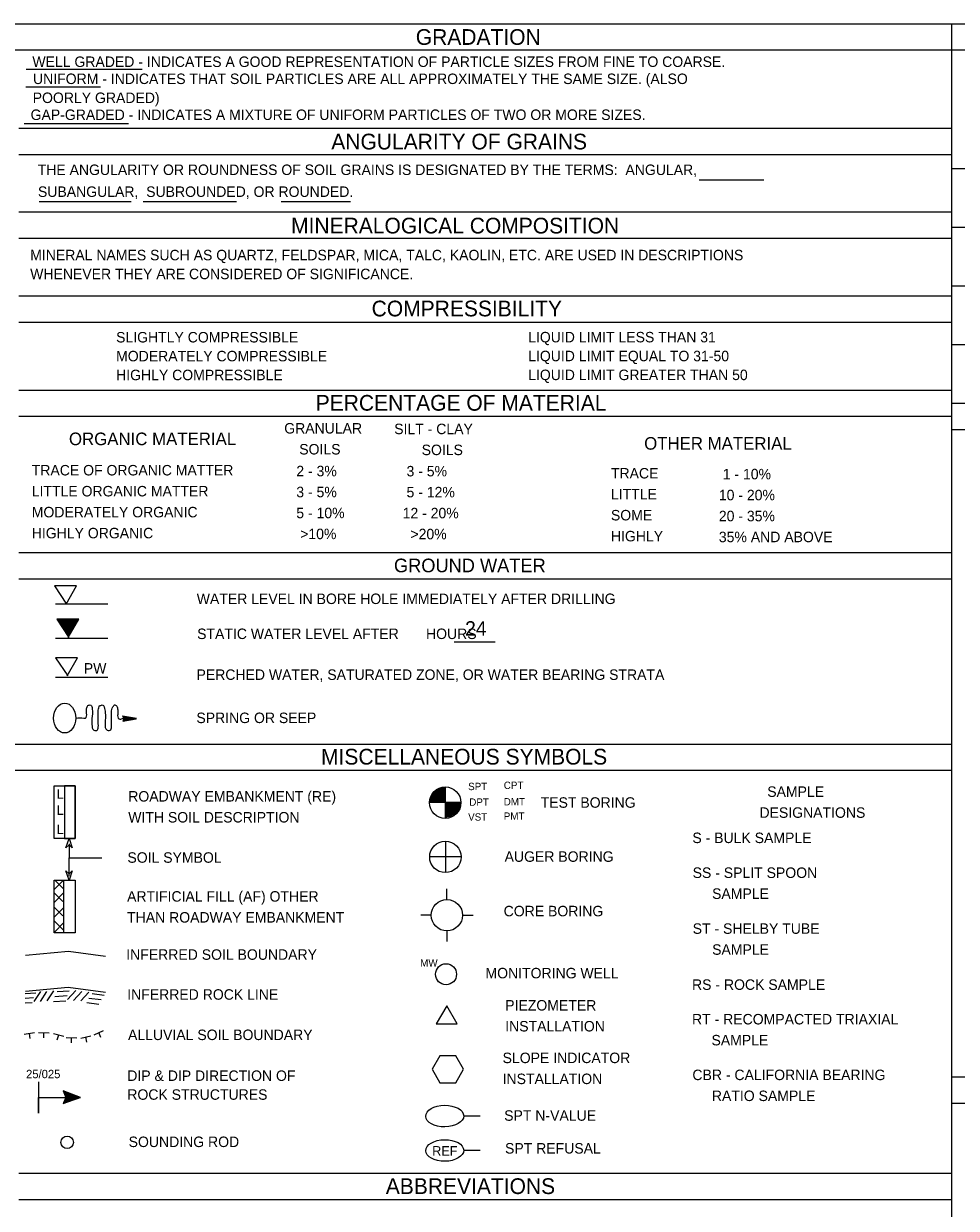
# Model space of a CAD drawing. Extents: x 278710 to 279187, y 171464 to 171625.
# Drawn here: x 279043.27 to 279081.88, y 171516.98 to 171566.02 of the extents above; entities that cross this region are included whole.
import ezdxf

# ---------------------------------------------------------------- set-up
doc = ezdxf.new("R2010")
doc.units = 0
doc.layers.add('Prop Strc Sect_ Misc - User Comment (Tx - small)', color=7, linetype='Continuous')

msp = doc.modelspace()

# ---------------------------------------------------------------- linework, layer by layer
at = {"layer": 'Prop Strc Sect_ Misc - User Comment (Tx - small)'}
for p, q in [((279005.33, 171566.02), (279158.027, 171566.02)), ((279081.678, 171566.02), (279081.678, 171485.806)), ((279005.33, 171564.936), (279158.027, 171564.936)), ((279043.374, 171564.138), (279048.18, 171564.138)), ((279043.357, 171563.4), (279046.445, 171563.4)), ((279043.287, 171561.882), (279047.616, 171561.882)), ((279081.678, 171561.682), (279043.07, 171561.682)), ((279081.678, 171560.598), (279043.07, 171560.598)), ((279121.332, 171560.012), (279081.678, 171560.012)), ((279071.241, 171559.557), (279073.916, 171559.557)), ((279043.914, 171558.659), (279047.726, 171558.659)), ((279048.219, 171558.663), (279052.076, 171558.663)), ((279053.933, 171558.659), (279056.796, 171558.659)), ((279081.678, 171558.212), (279043.07, 171558.212)), ((279121.332, 171557.583), (279081.678, 171557.583)), ((279081.678, 171557.127), (279043.07, 171557.127)), ((279121.332, 171555.154), (279081.678, 171555.154)), ((279081.678, 171554.741), (279043.07, 171554.741)), ((279081.678, 171553.657), (279043.07, 171553.657)), ((279121.332, 171552.724), (279081.678, 171552.724)), ((279081.678, 171550.837), (279043.07, 171550.837)), ((279121.332, 171550.295), (279081.678, 171550.295)), ((279081.678, 171549.753), (279043.07, 171549.753)), ((279121.332, 171549.21), (279081.678, 171549.21)), ((279081.678, 171544.113), (279043.07, 171544.113)), ((279079.076, 171544.113), (279043.07, 171544.113)), ((279081.678, 171543.029), (279043.07, 171543.029)), ((279044.589, 171542.005), (279046.758, 171542.005)), ((279044.589, 171540.587), (279046.758, 171540.587)), ((279061.09, 171540.435), (279062.794, 171540.435)), ((279044.589, 171538.973), (279046.758, 171538.973)), ((279047.938, 171537.251), (279047.365, 171537.359)), ((279047.365, 171537.359), (279047.426, 171537.255)), ((279047.426, 171537.255), (279047.374, 171537.142)), ((279047.374, 171537.142), (279047.924, 171537.246)), ((279047.413, 171537.233), (279047.664, 171537.281)), ((279047.413, 171537.233), (279047.664, 171537.281)), ((279047.413, 171537.229), (279047.664, 171537.277)), ((279047.413, 171537.225), (279047.664, 171537.272)), ((279047.413, 171537.22), (279047.664, 171537.268)), ((279047.413, 171537.216), (279047.664, 171537.264)), ((279047.413, 171537.216), (279047.664, 171537.264)), ((279047.417, 171537.212), (279047.669, 171537.259)), ((279047.417, 171537.207), (279047.669, 171537.255)), ((279047.417, 171537.203), (279047.669, 171537.251)), ((279047.417, 171537.199), (279047.669, 171537.246)), ((279047.417, 171537.194), (279047.669, 171537.242)), ((279047.417, 171537.19), (279047.669, 171537.238)), ((279047.417, 171537.19), (279047.669, 171537.238)), ((279047.421, 171537.272), (279047.677, 171537.229)), ((279047.421, 171537.272), (279047.677, 171537.229)), ((279047.421, 171537.268), (279047.677, 171537.225)), ((279047.421, 171537.186), (279047.673, 171537.233)), ((279047.421, 171537.181), (279047.673, 171537.229)), ((279047.421, 171537.177), (279047.673, 171537.225)), ((279047.426, 171537.303), (279047.682, 171537.259)), ((279047.426, 171537.298), (279047.682, 171537.255)), ((279047.426, 171537.294), (279047.682, 171537.251)), ((279047.426, 171537.29), (279047.682, 171537.246)), ((279047.426, 171537.285), (279047.682, 171537.242)), ((279047.426, 171537.281), (279047.682, 171537.238)), ((279047.43, 171537.324), (279047.686, 171537.281)), ((279047.43, 171537.316), (279047.686, 171537.272)), ((279047.43, 171537.311), (279047.686, 171537.268)), ((279047.43, 171537.307), (279047.686, 171537.264)), ((279047.434, 171537.329), (279047.69, 171537.285)), ((279047.439, 171537.337), (279047.907, 171537.251)), ((279047.421, 171537.173), (279047.673, 171537.22)), ((279047.421, 171537.173), (279047.673, 171537.22)), ((279047.421, 171537.168), (279047.673, 171537.216)), ((279047.426, 171537.164), (279047.677, 171537.212)), ((279081.678, 171536.183), (279005.33, 171536.183)), ((279081.678, 171535.099), (279005.33, 171535.099)), ((279044.966, 171534.466), (279044.966, 171532.297)), ((279060.722, 171534.426), (279060.722, 171533.125)), ((279061.372, 171533.775), (279060.071, 171533.775)), ((279060.73, 171532.179), (279060.73, 171530.878)), ((279061.381, 171531.528), (279060.08, 171531.528)), ((279044.537, 171530.175), (279044.91, 171530.548)), ((279044.91, 171530.214), (279044.558, 171530.566)), ((279044.918, 171530.535), (279044.918, 171528.384)), ((279044.528, 171529.646), (279044.918, 171530.037)), ((279044.892, 171529.685), (279044.537, 171530.041)), ((279060.791, 171529.767), (279060.791, 171530.201)), ((279044.537, 171529.034), (279044.918, 171529.416)), ((279044.892, 171529.091), (279044.545, 171529.438)), ((279060.14, 171529.116), (279059.706, 171529.116)), ((279061.442, 171529.116), (279061.876, 171529.116)), ((279044.541, 171528.418), (279044.923, 171528.8)), ((279044.914, 171528.497), (279044.545, 171528.865)), ((279060.791, 171528.466), (279060.791, 171528.032)), ((279043.699, 171525.538), (279043.973, 171525.954)), ((279043.96, 171525.542), (279044.229, 171525.959)), ((279044.246, 171525.573), (279044.515, 171525.989)), ((279044.662, 171525.954), (279045.157, 171525.985)), ((279045.087, 171525.629), (279045.426, 171525.993)), ((279045.335, 171525.586), (279045.677, 171525.954)), ((279043.335, 171525.876), (279043.773, 171525.907)), ((279043.335, 171525.685), (279043.682, 171525.707)), ((279043.335, 171525.482), (279043.621, 171525.499)), ((279044.506, 171525.547), (279045.009, 171525.577)), ((279044.558, 171525.751), (279045.066, 171525.785)), ((279045.634, 171525.564), (279045.964, 171525.928)), ((279045.881, 171525.499), (279046.38, 171525.434)), ((279045.964, 171525.685), (279046.476, 171525.629)), ((279046.107, 171525.868), (279046.601, 171525.811)), ((279043.287, 171524.193), (279043.717, 171524.254)), ((279043.534, 171524.007), (279043.504, 171524.224)), ((279043.886, 171524.258), (279044.32, 171524.245)), ((279044.098, 171524.037), (279044.103, 171524.25)), ((279044.506, 171524.215), (279044.927, 171524.106)), ((279044.662, 171523.95), (279044.719, 171524.163)), ((279045.035, 171524.054), (279045.469, 171524.033)), ((279045.244, 171523.829), (279045.252, 171524.041)), ((279045.63, 171524.028), (279046.055, 171524.119)), ((279045.886, 171523.864), (279045.842, 171524.076)), ((279046.181, 171524.167), (279046.58, 171524.341)), ((279046.467, 171524.054), (279046.38, 171524.254)), ((279081.678, 171522.419), (279121.332, 171522.419)), ((279081.678, 171521.334), (279121.332, 171521.334)), ((279061.489, 171520.814), (279062.175, 171520.814)), ((279061.489, 171519.391), (279062.175, 171519.391)), ((279043.07, 171518.437), (279081.678, 171518.437)), ((279043.07, 171517.352), (279081.678, 171517.352))]:
    msp.add_line(p, q, dxfattribs=at)
for points in [[(279045.027, 171541.996), (279045.461, 171542.747), (279044.55, 171542.747), (279045.048, 171541.996)], [(279045.113, 171540.613), (279045.547, 171541.363), (279044.636, 171541.363), (279045.135, 171540.613)], [(279044.68, 171541.337), (279045.517, 171541.337), (279045.122, 171540.669), (279044.68, 171541.337)], [(279044.727, 171541.311), (279045.478, 171541.311), (279045.122, 171540.708), (279044.736, 171541.289), (279045.452, 171541.289), (279045.122, 171540.747), (279044.771, 171541.268), (279045.413, 171541.268), (279045.122, 171540.795), (279044.818, 171541.242), (279045.369, 171541.242), (279045.118, 171540.842), (279044.858, 171541.216), (279045.326, 171541.211), (279045.113, 171540.886), (279044.901, 171541.19), (279045.291, 171541.19), (279045.113, 171540.925), (279044.944, 171541.168), (279045.252, 171541.168), (279045.113, 171540.973), (279044.988, 171541.15), (279045.218, 171541.15), (279045.118, 171541.012), (279045.035, 171541.129), (279045.174, 171541.129), (279045.113, 171541.033), (279045.074, 171541.107), (279045.144, 171541.111), (279045.113, 171541.077)], [(279045.07, 171539.021), (279045.504, 171539.771), (279044.593, 171539.771), (279045.092, 171539.021)], [(279047.374, 171537.355), (279047.434, 171537.251), (279047.434, 171537.342), (279047.378, 171537.355), (279047.43, 171537.268), (279047.43, 171537.337), (279047.387, 171537.346), (279047.426, 171537.281), (279047.426, 171537.333), (279047.395, 171537.337), (279047.421, 171537.303), (279047.421, 171537.294), (279047.421, 171537.324), (279047.404, 171537.329), (279047.421, 171537.329), (279047.413, 171537.316), (279047.439, 171537.246), (279047.43, 171537.246), (279047.426, 171537.242), (279047.382, 171537.146), (279047.426, 171537.155), (279047.439, 171537.246), (279047.43, 171537.238), (279047.391, 171537.151), (279047.421, 171537.159), (279047.43, 171537.233), (279047.4, 171537.155), (279047.417, 171537.164), (279047.421, 171537.207), (279047.408, 171537.159), (279047.434, 171537.159), (279047.916, 171537.251)], [(279047.69, 171537.281), (279047.89, 171537.251), (279047.682, 171537.212), (279047.69, 171537.277), (279047.864, 171537.251), (279047.686, 171537.22), (279047.695, 171537.268), (279047.838, 171537.246), (279047.816, 171537.255), (279047.69, 171537.272), (279047.69, 171537.225), (279047.825, 171537.246), (279047.695, 171537.264), (279047.69, 171537.233), (279047.803, 171537.246), (279047.695, 171537.259), (279047.699, 171537.238), (279047.781, 171537.251), (279047.695, 171537.255), (279047.695, 171537.238), (279047.751, 171537.255), (279047.699, 171537.246), (279047.695, 171537.229), (279047.755, 171537.238), (279047.699, 171537.285), (279047.781, 171537.268), (279047.69, 171537.285), (279047.434, 171537.255), (279047.46, 171537.246), (279047.469, 171537.251), (279047.469, 171537.255), (279047.491, 171537.255), (279047.491, 171537.259), (279047.447, 171537.32), (279047.53, 171537.303), (279047.525, 171537.316), (279047.439, 171537.333)], [(279047.439, 171537.259), (279047.478, 171537.251), (279047.434, 171537.242), (279047.538, 171537.264), (279047.439, 171537.272), (279047.525, 171537.255), (279047.504, 171537.272), (279047.434, 171537.324), (279047.63, 171537.285), (279047.686, 171537.277), (279047.682, 171537.207), (279047.673, 171537.242)], [(279060.079, 171533.796), (279060.717, 171533.804), (279060.079, 171533.809), (279060.114, 171533.813), (279060.717, 171533.822), (279060.079, 171533.83), (279060.713, 171533.843), (279060.088, 171533.848), (279060.713, 171533.861), (279060.084, 171533.874), (279060.717, 171533.882), (279060.097, 171533.895), (279060.717, 171533.908), (279060.101, 171533.921), (279060.713, 171533.934), (279060.101, 171533.947), (279060.717, 171533.952), (279060.118, 171533.973), (279060.717, 171533.973), (279060.123, 171533.995), (279060.717, 171533.995), (279060.131, 171534.021), (279060.721, 171534.017), (279060.149, 171534.047), (279060.717, 171534.043), (279060.162, 171534.078), (279060.721, 171534.065), (279060.188, 171534.108), (279060.721, 171534.095), (279060.201, 171534.134), (279060.717, 171534.121), (279060.227, 171534.164), (279060.717, 171534.156), (279060.253, 171534.195), (279060.717, 171534.182), (279060.279, 171534.225), (279060.726, 171534.208), (279060.318, 171534.26), (279060.717, 171534.242), (279060.361, 171534.29), (279060.717, 171534.277), (279060.418, 171534.32), (279060.717, 171534.312), (279060.491, 171534.355), (279060.713, 171534.346), (279060.582, 171534.373), (279060.717, 171534.381), (279060.652, 171534.394)], [(279061.36, 171533.759), (279060.722, 171533.75), (279061.36, 171533.746), (279061.325, 171533.741), (279060.722, 171533.733), (279061.36, 171533.724), (279060.726, 171533.711), (279061.351, 171533.706), (279060.726, 171533.693), (279061.355, 171533.68), (279060.722, 171533.672), (279061.342, 171533.659), (279060.722, 171533.646), (279061.338, 171533.633), (279060.726, 171533.62), (279061.338, 171533.607), (279060.722, 171533.602), (279061.321, 171533.581), (279060.722, 171533.581), (279061.316, 171533.559), (279060.722, 171533.559), (279061.308, 171533.533), (279060.718, 171533.537), (279061.29, 171533.507), (279060.722, 171533.511), (279061.277, 171533.477), (279060.718, 171533.49), (279061.251, 171533.446), (279060.718, 171533.459), (279061.238, 171533.42), (279060.722, 171533.433), (279061.212, 171533.39), (279060.722, 171533.398), (279061.186, 171533.359), (279060.722, 171533.372), (279061.16, 171533.329), (279060.713, 171533.346), (279061.121, 171533.294), (279060.722, 171533.312), (279061.078, 171533.264), (279060.722, 171533.277), (279061.021, 171533.234), (279060.722, 171533.242), (279060.948, 171533.199), (279060.726, 171533.208), (279060.856, 171533.182), (279060.722, 171533.173), (279060.787, 171533.16)], [(279045.148, 171532.071), (279045.148, 171531.49), (279046.511, 171531.49)], [(279045.148, 171530.726), (279045.148, 171531.494)], [(279043.344, 171527.46), (279045.122, 171527.629), (279046.658, 171527.421)], [(279043.339, 171525.972), (279045.118, 171526.141), (279046.653, 171525.933)], [(279060.353, 171524.614), (279061.22, 171524.614), (279060.787, 171525.364), (279060.353, 171524.614)], [(279060.505, 171522.172), (279061.155, 171522.172), (279061.481, 171522.736), (279061.155, 171523.3), (279060.505, 171523.3), (279060.179, 171522.736), (279060.505, 171522.172)], [(279043.881, 171522.219), (279043.881, 171520.918), (279043.881, 171521.569), (279045.617, 171521.569), (279044.91, 171521.842), (279045.018, 171521.569), (279044.914, 171521.343), (279044.901, 171521.317), (279045.608, 171521.564), (279045.035, 171521.556), (279044.927, 171521.334), (279045.543, 171521.547), (279045.166, 171521.547), (279045.04, 171521.543), (279044.949, 171521.356), (279045.482, 171521.538), (279045.053, 171521.538), (279044.979, 171521.378), (279045.443, 171521.538), (279045.014, 171521.521), (279045.066, 171521.512), (279044.992, 171521.387), (279045.07, 171521.538), (279045.391, 171521.521), (279045.018, 171521.4), (279045.087, 171521.517), (279045.348, 171521.517), (279045.044, 171521.426), (279045.092, 171521.508), (279045.278, 171521.508), (279045.074, 171521.443), (279045.096, 171521.504), (279045.209, 171521.504), (279045.1, 171521.465), (279045.113, 171521.491), (279045.166, 171521.486), (279045.126, 171521.478), (279045.04, 171521.439), (279045.066, 171521.495), (279045.018, 171521.404), (279044.966, 171521.378), (279045.035, 171521.521), (279044.988, 171521.69), (279044.931, 171521.816), (279045.569, 171521.577), (279045.027, 171521.586), (279045.526, 171521.595), (279044.957, 171521.799), (279045.035, 171521.577), (279045.456, 171521.599), (279045.044, 171521.599), (279044.983, 171521.777), (279045.014, 171521.755), (279045.044, 171521.612), (279045.031, 171521.755), (279045.465, 171521.603), (279045.057, 171521.612), (279045.04, 171521.729), (279045.404, 171521.621), (279045.066, 171521.625), (279045.352, 171521.625), (279045.053, 171521.716), (279045.3, 171521.625), (279045.044, 171521.699), (279045.07, 171521.642), (279045.244, 171521.621), (279045.109, 171521.651), (279045.053, 171521.647), (279045.061, 171521.673), (279045.248, 171521.638), (279045.07, 171521.682), (279045.035, 171521.751), (279045.222, 171521.677), (279044.983, 171521.773), (279045.044, 171521.703), (279045.001, 171521.747), (279045.018, 171521.716), (279045.027, 171521.695)]]:
    msp.add_lwpolyline(points, dxfattribs=at)
for points in [[(279044.532, 171534.466), (279045.4, 171534.466), (279045.4, 171532.297), (279044.532, 171532.297)], [(279044.966, 171532.297), (279045.4, 171532.297), (279045.4, 171534.466), (279044.966, 171534.466)], [(279045.018, 171531.902), (279045.148, 171532.292), (279045.278, 171531.902), (279045.148, 171532.032)], [(279045.278, 171530.956), (279045.148, 171530.566), (279045.018, 171530.956), (279045.148, 171530.826)], [(279044.532, 171530.561), (279045.4, 171530.561), (279045.4, 171528.392), (279044.532, 171528.392)]]:
    msp.add_lwpolyline(points, close=True, dxfattribs=at)
for centre, radius in [((279060.722, 171533.775), 0.651), ((279060.73, 171531.528), 0.651), ((279060.791, 171529.116), 0.651), ((279060.756, 171526.67), 0.434), ((279045.07, 171519.712), 0.26)]:
    msp.add_circle(centre, radius, dxfattribs=at)
for centre, major_axis, ratio in [((279044.969, 171537.276), (0, -0.618), 0.743839), ((279060.702, 171520.798), (0.787, 0.011), 0.568627), ((279060.702, 171519.375), (0.787, 0.011), 0.568627)]:
    msp.add_ellipse(centre, major_axis=major_axis, ratio=ratio, dxfattribs=at)
msp.add_spline([(279045.43, 171537.277), (279045.76, 171537.272), (279045.829, 171537.272), (279045.873, 171537.481), (279045.873, 171537.676), (279045.894, 171537.736), (279045.925, 171537.789), (279046.046, 171537.81), (279046.111, 171537.663), (279046.098, 171537.251), (279046.098, 171537.003), (279046.111, 171536.878), (279046.172, 171536.778), (279046.263, 171536.756), (279046.298, 171536.765), (279046.358, 171536.899), (279046.358, 171537.042), (279046.358, 171537.467), (279046.358, 171537.602), (279046.38, 171537.706), (279046.411, 171537.789), (279046.463, 171537.797), (279046.523, 171537.819), (279046.575, 171537.797), (279046.606, 171537.736), (279046.649, 171537.498), (279046.649, 171537.077), (279046.649, 171536.96), (279046.666, 171536.825), (279046.732, 171536.778), (279046.814, 171536.765), (279046.875, 171536.795), (279046.905, 171536.878), (279046.905, 171537.003), (279046.905, 171537.489), (279046.905, 171537.58), (279046.935, 171537.684), (279046.966, 171537.736), (279047, 171537.789), (279047.031, 171537.819), (279047.07, 171537.81), (279047.122, 171537.767), (279047.152, 171537.697), (279047.165, 171537.615), (279047.165, 171537.428), (279047.165, 171537.324), (279047.226, 171537.242), (279047.361, 171537.251), (279047.608, 171537.251), (279047.938, 171537.251)], degree=3, dxfattribs=at)

# ---------------------------------------------------------------- texts
for s, height, p in [('GRADATION', 0.6507, (279059.503, 171565.144)), ('WELL GRADED - INDICATES A GOOD REPRESENTATION OF PARTICLE SIZES FROM FINE TO COARSE.', 0.43381, (279043.63, 171564.229)), ('UNIFORM - INDICATES THAT SOIL PARTICLES ARE ALL APPROXIMATELY THE SAME SIZE. (ALSO', 0.43381, (279043.656, 171563.522)), ('POORLY GRADED)', 0.43381, (279043.643, 171562.736)), ('GAP-GRADED - INDICATES A MIXTURE OF UNIFORM PARTICLES OF TWO OR MORE SIZES.', 0.43381, (279043.556, 171562.034)), ('ANGULARITY OF GRAINS', 0.6507, (279056.006, 171560.815)), ('THE ANGULARITY OR ROUNDNESS OF SOIL GRAINS IS DESIGNATED BY THE TERMS:  ANGULAR,', 0.43381, (279043.849, 171559.756)), ('SUBANGULAR,  SUBROUNDED, OR ROUNDED.', 0.43381, (279043.86, 171558.849)), ('MINERALOGICAL COMPOSITION', 0.6507, (279054.34, 171557.336)), ('MINERAL NAMES SUCH AS QUARTZ, FELDSPAR, MICA, TALC, KAOLIN, ETC. ARE USED IN DESCRIPTIONS ', 0.43381, (279043.539, 171556.225)), ('WHENEVER THEY ARE CONSIDERED OF SIGNIFICANCE.', 0.43381, (279043.539, 171555.444)), ('COMPRESSIBILITY', 0.6507, (279057.676, 171553.904)), ('SLIGHTLY COMPRESSIBLE', 0.43381, (279047.096, 171552.824)), ('LIQUID LIMIT LESS THAN 31', 0.43381, (279064.157, 171552.828)), ('MODERATELY COMPRESSIBLE', 0.43381, (279047.096, 171552.043)), ('LIQUID LIMIT EQUAL TO 31-50', 0.43381, (279064.157, 171552.047)), ('HIGHLY COMPRESSIBLE', 0.43381, (279047.096, 171551.262)), ('LIQUID LIMIT GREATER THAN 50', 0.43381, (279064.157, 171551.266)), ('PERCENTAGE OF MATERIAL', 0.6507, (279055.36, 171550)), ('GRANULAR', 0.4338, (279054.058, 171549.054)), ('ORGANIC MATERIAL', 0.52056, (279045.144, 171548.573)), ('SILT - CLAY', 0.43381, (279058.61, 171549.028)), (' SOILS', 0.4338, (279054.518, 171548.187)), ('SOILS', 0.4338, (279059.747, 171548.161)), ('OTHER MATERIAL', 0.52056, (279068.959, 171548.386)), ('TRACE OF ORGANIC MATTER', 0.43381, (279043.604, 171547.319)), ('2 - 3%', 0.4338, (279054.557, 171547.284)), (' 3 - 5%', 0.4338, (279058.96, 171547.28)), ('TRACE', 0.4338, (279067.584, 171547.193)), (' 1 - 10%', 0.4338, (279072.052, 171547.159)), ('LITTLE ORGANIC MATTER', 0.43381, (279043.604, 171546.451)), ('3 - 5%', 0.4338, (279054.557, 171546.417)), (' 5 - 12%', 0.4338, (279058.96, 171546.412)), ('LITTLE', 0.4338, (279067.584, 171546.326)), ('10 - 20%', 0.4338, (279072.052, 171546.291)), ('MODERATELY ORGANIC', 0.43381, (279043.604, 171545.584)), ('5 - 10%', 0.4338, (279054.557, 171545.549)), ('12 - 20%', 0.4338, (279058.96, 171545.545)), ('SOME', 0.4338, (279067.584, 171545.458)), ('20 - 35%', 0.4338, (279072.052, 171545.423)), ('HIGHLY ORGANIC', 0.43381, (279043.604, 171544.716)), (' >10%', 0.4338, (279054.557, 171544.682)), ('  >20%', 0.4338, (279058.96, 171544.677)), ('HIGHLY', 0.4338, (279067.584, 171544.59)), ('35% AND ABOVE', 0.43381, (279072.052, 171544.556)), ('GROUND WATER', 0.56395, (279058.6, 171543.311)), ('WATER LEVEL IN BORE HOLE IMMEDIATELY AFTER DRILLING', 0.43381, (279050.434, 171541.996)), ('24', 0.6, (279061.543, 171540.686)), ('STATIC WATER LEVEL AFTER       HOURS', 0.43381, (279050.451, 171540.547)), ('PW', 0.4338, (279045.76, 171539.116)), ('PERCHED WATER, SATURATED ZONE, OR WATER BEARING STRATA', 0.43381, (279050.426, 171538.856)), ('SPRING OR SEEP', 0.43381, (279050.42, 171537.068)), ('MISCELLANEOUS SYMBOLS', 0.6507, (279055.581, 171535.351)), ('L', 0.39, (279044.639, 171533.937)), ('SPT', 0.3037, (279061.672, 171534.292)), ('CPT', 0.3037, (279063.147, 171534.34)), ('  SAMPLE', 0.4338, (279073.733, 171534.014)), ('ROADWAY EMBANKMENT (RE)', 0.43381, (279047.599, 171533.819)), ('DPT', 0.3037, (279061.719, 171533.646)), ('DMT', 0.3037, (279063.147, 171533.659)), ('TEST BORING', 0.43381, (279064.674, 171533.563)), ('L', 0.39, (279044.639, 171533.269)), ('WITH SOIL DESCRIPTION', 0.43381, (279047.599, 171532.952)), ('VST', 0.3037, (279061.672, 171533.03)), ('PMT', 0.3037, (279063.147, 171533.064)), ('DESIGNATIONS', 0.43381, (279073.733, 171533.146)), ('L', 0.39, (279044.639, 171532.479)), ('S - BULK SAMPLE', 0.43381, (279070.956, 171532.101)), ('SOIL SYMBOL', 0.43381, (279047.564, 171531.286)), ('AUGER BORING', 0.43381, (279063.181, 171531.325)), ('SS - SPLIT SPOON', 0.43381, (279070.966, 171530.657)), ('ARTIFICIAL FILL (AF) OTHER', 0.43381, (279047.551, 171529.676)), ('     SAMPLE', 0.43381, (279070.966, 171529.79)), ('CORE BORING', 0.43381, (279063.142, 171529.069)), ('THAN ROADWAY EMBANKMENT', 0.43381, (279047.551, 171528.809)), ('ST - SHELBY TUBE', 0.43381, (279070.968, 171528.344)), ('     SAMPLE', 0.43381, (279070.968, 171527.477)), ('INFERRED SOIL BOUNDARY', 0.43381, (279047.515, 171527.269)), ('   MONITORING WELL', 0.43381, (279061.906, 171526.501)), ('RS - ROCK SAMPLE', 0.43381, (279070.941, 171526.024)), ('INFERRED ROCK LINE', 0.43381, (279047.556, 171525.616)), ('PIEZOMETER', 0.4338, (279063.207, 171525.169)), ('RT - RECOMPACTED TRIAXIAL', 0.43381, (279070.941, 171524.593)), ('INSTALLATION', 0.43381, (279063.207, 171524.302)), ('ALLUVIAL SOIL BOUNDARY', 0.43381, (279047.59, 171523.946)), ('     SAMPLE', 0.43381, (279070.941, 171523.726)), ('SLOPE INDICATOR', 0.43381, (279063.099, 171522.992)), ('25/025', 0.347, (279043.37, 171522.367)), ('DIP & DIP DIRECTION OF ', 0.43381, (279047.56, 171522.255)), ('INSTALLATION', 0.43381, (279063.099, 171522.124)), ('CBR - CALIFORNIA BEARING', 0.43381, (279070.957, 171522.288)), ('ROCK STRUCTURES', 0.43381, (279047.56, 171521.474)), ('     RATIO SAMPLE', 0.43381, (279070.957, 171521.421)), ('SPT N-VALUE', 0.43381, (279063.164, 171520.606)), ('SOUNDING ROD', 0.43381, (279047.615, 171519.517)), ('SPT REFUSAL', 0.43381, (279063.199, 171519.248)), ('REF', 0.3904, (279060.184, 171519.165)), ('ABBREVIATIONS', 0.6507, (279058.262, 171517.573))]:
    msp.add_text(s, height=height, dxfattribs=at).set_placement(p)
msp.add_text('MW', height=0.3037, rotation=360, dxfattribs=at).set_placement((279059.687, 171526.989))

doc.saveas('drawing.dxf')
